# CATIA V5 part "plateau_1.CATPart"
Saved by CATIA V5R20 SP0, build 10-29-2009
Part number: plateau_1
Publications: "plateau1_ecarth", "plateau1_H", "plateau1_l", "plateau1_pivotinf", "plateau1_pivotsup"
Bounding box of the stored display mesh (mm): x -10 to 110, y -400 to -50, z -50 to 100
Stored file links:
  C:\Users\Noëllie\Documents\IFMA\2A\S3\IAO\Projet Artobolevski\Catia\plateau_1.CATPart
  C:\Users\Noëllie\Documents\IFMA\2A\S3\IAO\Projet Artobolevski\Catia\Artobolevski 782.CATProduct
  C:\Users\Noëllie\Documents\IFMA\2A\S3\IAO\Projet Artobolevski\Catia\plateau_2.CATPart
  C:\Users\Noëllie\Documents\IFMA\2A\S3\IAO\Projet Artobolevski\Catia\support_1.CATPart
  C:\Users\Noëllie\Documents\IFMA\2A\S3\IAO\Projet Artobolevski\Catia\support_2.CATPart
  C:\Users\Noëllie\Documents\IFMA\2A\S3\IAO\Projet Artobolevski\Catia\Squelette_general.CATPart
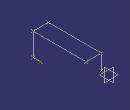
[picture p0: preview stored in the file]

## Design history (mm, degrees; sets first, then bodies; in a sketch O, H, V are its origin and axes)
Set1
  Point1 "C1": linked copy from another document
  Point2 "pp_11": linked copy from another document
  Point3 "B2g": linked copy from another document
  Point4 to Point7: linked copy from another document
Body1 (main body)
  Line1 "plateau1_pivotinf": type PtDir, RefPoint Point1, Direction yz-plane, Start 10, End -10
  Line2 "plateau1_h": type PtPt, FirstPoint Point2, SecondPoint Point3
  Line3 "plateau1_pivotsup": type PtDir, RefPoint Point3, Direction yz-plane, Start 10, End -10
  Line4 "plateau1_H": type PtPt, FirstPoint Point4, SecondPoint Point5
  Line5 "plateau1_eh": type PtPt, FirstPoint Point5, SecondPoint Point1
  Line6: type PtPt, FirstPoint Point4, SecondPoint Point6
  Line7: type PtPt, FirstPoint Point6, SecondPoint Point2
  Line8: type PtPt, FirstPoint Point2, SecondPoint Point7
  Line9: type PtPt, FirstPoint Point4, SecondPoint Point7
